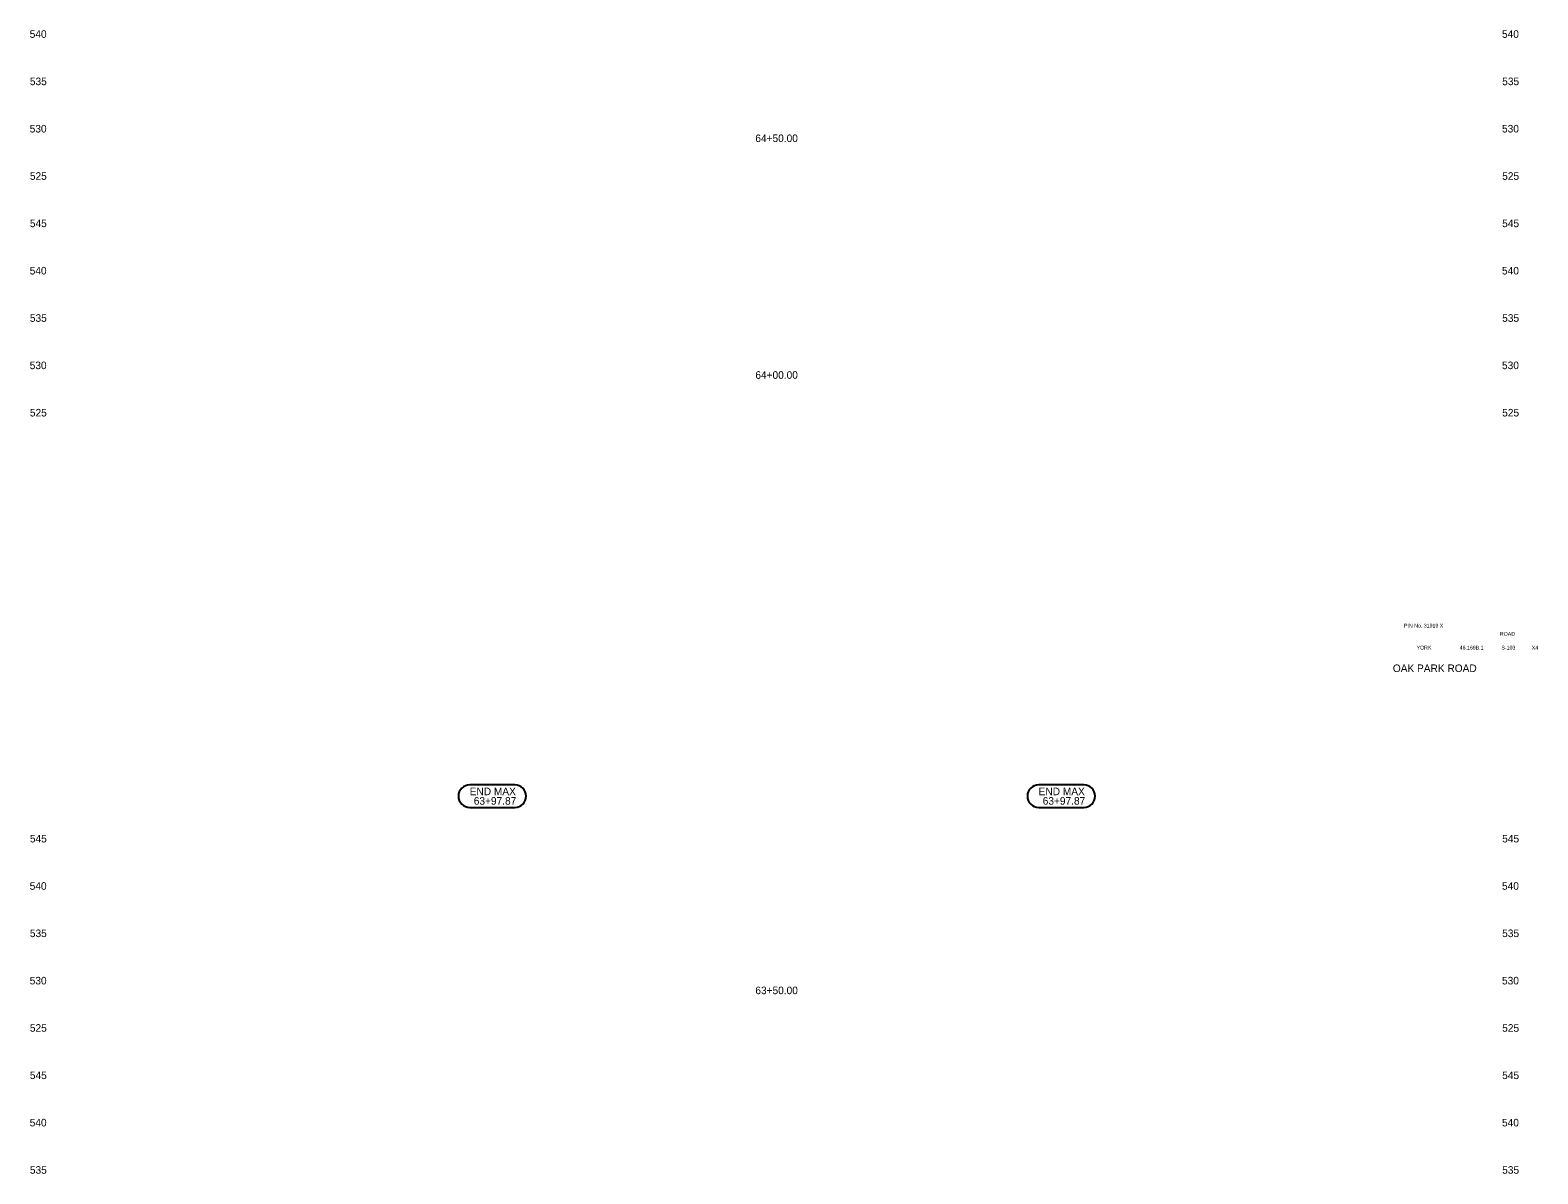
# Model space of a CAD drawing. Extents: x 1001 to 1160, y 1010 to 2023.
# Drawn here: x 1001.2 to 1160.4, y 1390.1 to 1510.9 of the extents above; entities that cross this region are included whole.
import ezdxf

# ---------------------------------------------------------------- set-up
doc = ezdxf.new("R2010")
doc.units = 0
for name, color, linetype in [('RD_SHT_TX', 7, 'Continuous'), ('RD_XS_TX_Elev_EX', 7, 'Continuous'), ('RD_XS_TX_Misc', 7, 'Continuous'), ('RD_XS_TX_Notes', 7, 'Continuous'), ('RD_XS_TX_Station', 7, 'Continuous')]:
    doc.layers.add(name, color=color, linetype=linetype)

msp = doc.modelspace()

# ---------------------------------------------------------------- linework, layer by layer
at = {"layer": 'RD_XS_TX_Misc'}
for p, q in [((1052.37, 1431.19), (1047.61, 1431.19)), ((1112.46, 1431.19), (1107.7, 1431.19)), ((1047.61, 1428.79), (1052.37, 1428.79)), ((1107.7, 1428.79), (1112.46, 1428.79))]:
    msp.add_line(p, q, dxfattribs=at)
for centre, start, end in [((1047.61, 1429.99), 90, 270), ((1052.37, 1429.99), 270, 90), ((1107.7, 1429.99), 90, 270), ((1112.46, 1429.99), 270, 90)]:
    msp.add_arc(centre, 1.2, start, end, dxfattribs=at)

# ---------------------------------------------------------------- texts
at = {"layer": 'RD_SHT_TX'}
for s, height, p in [('PIN No. 31919 X', 0.4, (1146.28, 1447.8)), ('YORK', 0.4, (1147.6, 1445.48)), ('46.169B.1', 0.4, (1152.16, 1445.48)), ('ROAD', 0.4, (1156.41, 1446.93)), ('S-103', 0.4, (1156.57, 1445.48)), ('X4', 0.4, (1159.78, 1445.48)), ('OAK PARK ROAD', 0.8, (1145.1, 1443.1))]:
    msp.add_text(s, height=height, dxfattribs=at).set_placement(p)
at = {"layer": 'RD_XS_TX_Elev_EX'}
for s, p in [('540', (1001.13, 1510.1)), ('540', (1156.63, 1510.1)), ('535', (1001.15, 1505.1)), ('535', (1156.65, 1505.1)), ('530', (1001.13, 1500.1)), ('530', (1156.63, 1500.1)), ('525', (1001.15, 1495.1)), ('525', (1156.65, 1495.1)), ('545', (1001.15, 1490.1)), ('545', (1156.65, 1490.1)), ('540', (1001.13, 1485.1)), ('540', (1156.63, 1485.1)), ('535', (1001.15, 1480.1)), ('535', (1156.65, 1480.1)), ('530', (1001.13, 1475.1)), ('530', (1156.63, 1475.1)), ('525', (1001.15, 1470.1)), ('525', (1156.65, 1470.1)), ('545', (1001.15, 1425.1)), ('545', (1156.65, 1425.1)), ('540', (1001.13, 1420.1)), ('540', (1156.63, 1420.1)), ('535', (1001.15, 1415.1)), ('535', (1156.65, 1415.1)), ('530', (1001.13, 1410.1)), ('530', (1156.63, 1410.1)), ('525', (1001.15, 1405.1)), ('525', (1156.65, 1405.1)), ('545', (1001.15, 1400.1)), ('545', (1156.65, 1400.1)), ('540', (1001.13, 1395.1)), ('540', (1156.63, 1395.1)), ('535', (1001.15, 1390.1)), ('535', (1156.65, 1390.1))]:
    msp.add_text(s, height=0.8, dxfattribs=at).set_placement(p)
at = {"layer": 'RD_XS_TX_Notes'}
for s, p in [('END MAX', (1047.6, 1430.09)), ('END MAX', (1107.69, 1430.09)), ('63+97.87', (1048.03, 1429.09)), ('63+97.87', (1108.12, 1429.09))]:
    msp.add_text(s, height=0.8, dxfattribs=at).set_placement(p)
at = {"layer": 'RD_XS_TX_Station'}
for s, p in [('64+50.00', (1077.77, 1499.09)), ('64+00.00', (1077.77, 1474.08)), ('63+50.00', (1077.77, 1409.07))]:
    msp.add_text(s, height=0.8, dxfattribs=at).set_placement(p)

doc.saveas('drawing.dxf')
